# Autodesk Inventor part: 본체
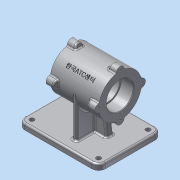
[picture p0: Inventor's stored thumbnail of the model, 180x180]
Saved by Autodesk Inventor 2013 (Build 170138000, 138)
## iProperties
Created: 2015-12
Part Number: 본체
Material: 알루미늄 6061
Document SubType Name: Modeling
Designer: Administrator
Density: 2.71 g/cm^3
Mass: 1142.91 g
Surface Area: 797.148 cm^2
Volume: 421.737 cm^3
Author: Administrator
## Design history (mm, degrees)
sketch "스케치1"
  geometry: L1 (-70, 55)-(70, 55); L2 (70, 55)-(70, -55); L3 (70, -55)-(-70, -55); L4 (-70, -55)-(-70, 55); 3 further points
  constraints: 8 end point, 2 midpoint, 2 parallel, 1 horizontal, 1 horizontal alignment, 1 perpendicular, 1 vertical alignment
  dimensions: "d0" = 140 distance of L1.start L1.end; "d2" = 110 distance of L1.end L2.end
extrude "돌출1" new body sketch "스케치1" distance "d3" = 10; taper "d4" = 0 deg
node "작업 평면1"
sketch "스케치2"
  geometry: L1 (0, 110)-(0, 0) reference; C1 r 37 at (80, 55); 2 further points
  constraints: 1 centre point, 1 horizontal alignment, 1 midpoint
  dimensions: "d6" = 74 diameter of C1; "d111" = 80 distance of point (0, 55) C1.centre
extrude "돌출2" join sketch "스케치2" stored distance "d8" = 85; taper "d9" = 0 deg
sketch "스케치3"
  geometry: L1 (0, 0)-(0, 110) reference; L2 (0, 0)-(10, 0) reference; L3 (10, 110)-(10, 0) reference; L4 (0, 110)-(10, 110) reference; L5 (0, 110)-(10, 110) reference; L6 (10, 110)-(10, 0) reference; L7 (10, 0)-(0, 0) reference; L8 (0, 0)-(0, 110) reference; L9 (10, 18)-(80, 18); L10 (10, 92)-(80, 92); L11 (80, 18)-(80, 92); A1 r 37 centre (80, 55) between (80, 92) and (80, 18) reference; 1 further point
  constraints: 6 end point, 2 perpendicular, 2 point on circle, 2 point on line, 2 tangent, 1 parallel
extrude "돌출3" join sketch "스케치3" stored distance "d10" = 8; taper "d11" = 0 deg
sketch "스케치4"
  geometry: L1 (70, 10)-(70, 0) reference; L2 (70, 0)-(-70, 0) reference; L3 (-70, 0)-(-70, 10) reference; L4 (-70, 10)-(-14, 10) reference; L5 (-14, 10)-(-14, 43) reference; L6 (-14, 43)-(-52.5, 43) reference; L7 (-52.5, 43)-(-52.5, 117) reference; L8 (-52.5, 117)-(32.5, 117) reference; L9 (32.5, 117)-(32.5, 43) reference; L10 (32.5, 43)-(-6, 43) reference; L11 (-6, 43)-(-6, 10) reference; L12 (-6, 10)-(70, 10) reference; L13 (-28.245, 65.019)-(8.245, 65.019); L14 (-28.245, 65.019)-(-35, 10); L15 (8.245, 65.019)-(15, 10); L16 (-35, 10)-(15, 10); 3 further points
  constraints: 8 end point, 2 midpoint, 2 point on line, 1 collinear, 1 parallel, 1 vertical alignment
  dimensions: "d15" = 97 deg angle of L4 L14; "d16" = 97 deg angle of L12 L15; "d17" = 50 distance of L15.end L14.end; "d19" = 55.01908 distance between parallel lines of L12 L13
extrude "돌출4" join sketch "스케치4" stored distance "d20" = 12; taper "d21" = 0 deg
sketch "스케치5"
  geometry: L1 (70, -55)-(70, 55) reference; L2 (70, 55)-(80, 55) reference; L3 (80, 55)-(80, -55) reference; L4 (80, -55)-(70, -55) reference; L5 (-37, -7)-(-36.332, -7); L6 (-37, 7)-(-36.332, 7); A1 r 37 centre (0, 0) between (-37, 0) and (-36.332, -7) reference; A2 r 7 centre (-37, 0) between (-37, 7) and (-37, -7); 1 further point
  constraints: 5 point on circle, 4 end point, 2 parallel, 2 tangent, 1 centre point, 1 horizontal alignment
  dimensions: "d22" = 14 diameter of A2
extrude "돌출5" join sketch "스케치5" distance "d25" = 15; taper "d26" = 0 deg
feature "면 기울기1" dims angle "d27" = 20 deg
hole "구멍1" diameter "d33" = 42; stored, may be unused: countersink angle "d37" = 90 deg, drill point angle "d39" = 0 deg; dims "d31" = 10, "d32" = 10, "d34" = 6, "d35" = 47, "d36" = 22, "d38" = 63
hole "구멍2" diameter "d42" = 47; stored, may be unused: countersink angle "d46" = 90 deg, drill point angle "d48" = 0 deg; dims "d40" = 10, "d41" = 10, "d43" = 6, "d44" = 47, "d45" = 22, "d47" = 22
hole "구멍3" diameter "d51" = 3.242; stored, may be unused: countersink angle "d55" = 90 deg, drill point angle "d57" = 118 deg; dims "d49" = 10, "d50" = 10, "d52" = 9, "d53" = 47, "d54" = 22, "d56" = 11
hole "구멍4" diameter "d63" = 3.242; stored, may be unused: countersink angle "d67" = 90 deg, drill point angle "d69" = 118 deg; dims "d61" = 10, "d62" = 10, "d64" = 9, "d65" = 47, "d66" = 22, "d68" = 11
sketch "스케치6"
  geometry: L1 (6, -6)-(-15, -6) reference; L2 (-15, -6)-(-15, 6) reference; L3 (-15, 6)-(6, 6) reference; L4 (6, 6)-(6, 37) reference; L5 (6, 37)-(14, 37) reference; L6 (14, 37)-(14, 6) reference; L7 (14, 6)-(35, 6) reference; L8 (35, 6)-(35, -6) reference; L9 (35, -6)-(14, -6) reference; L10 (14, -6)-(14, -37) reference; L11 (14, -37)-(6, -37) reference; L12 (6, -37)-(6, -6) reference; L13 (70, 55)-(70, -55) reference; L14 (70, -55)-(-70, -55) reference; L15 (-70, -55)-(-70, 55) reference; L16 (-70, 55)-(70, 55) reference; C1 r 4 at (-58, 43); C2 r 4 at (58, 43); C3 r 4 at (-58, -43); C4 r 4 at (58, -43); 1 further point
  constraints: 4 centre point, 3 equal radius, 2 horizontal alignment, 2 vertical alignment
  dimensions: "d73" = 12 distance from line of C1.centre L15; "d74" = 12 distance from line of L16 C1.centre; "d76" = 116 distance of C2.centre C1.centre; "d77" = 86 distance of C1.centre C3.centre; "d78" = 8 diameter of C1
  node "절단 모서리 투영4"
extrude "돌출6" cut sketch "스케치6" stored distance "d79" = 15; taper "d80" = 0 deg
extrude "돌출7" cut sketch "스케치6" stored distance "d81" = 15; taper "d82" = 0 deg
extrude "돌출8" cut sketch "스케치6" stored distance "d83" = 15; taper "d84" = 0 deg
extrude "돌출9" cut sketch "스케치6" distance "d85" = 15; taper "d86" = 0 deg
fillet "모깎기1" dims "d87" = 12
fillet "모깎기2" dims "d88" = 3
fillet "모깎기3" dims "d89" = 3
fillet "모깎기4" dims "d90" = 3
fillet "모깎기5" dims "d91" = 3
fillet "모깎기6" dims "d92" = 3
fillet "모깎기7" dims "d93" = 3
fillet "모깎기8" dims "d94" = 3
fillet "모깎기9" dims "d95" = 3
fillet "모깎기10" dims "d96" = 0.3
chamfer "모따기1" distance "d97" = 1; stored, may be unused: second distance "d98" = 2, angle "d99" = 45 deg
sketch "스케치10"
  geometry: L1 (13, 92)-(80, 92) reference; L2 (80, 18)-(13, 18) reference; L3 (10, 15)-(10, 3) reference; L4 (7, 0)-(0, 0) reference; L5 (0, 0)-(0, 110) reference; L6 (0, 110)-(7, 110) reference; L7 (10, 107)-(10, 95) reference; C1 r 21 at (80, 55) reference; A1 r 3 centre (13, 95) between (10, 95) and (13, 92) reference; A2 r 37 centre (80, 55) between (80, 18) and (80, 92) reference; A3 r 3 centre (13, 15) between (13, 18) and (10, 15) reference; A4 r 3 centre (7, 3) between (7, 0) and (10, 3) reference; A5 r 3 centre (7, 107) between (10, 107) and (7, 110) reference; 3 further points
  constraints: 1 coincident, 1 point on circle
  dimensions: "d106" = 45 deg dimension on A2.centre point (106.163, 28.837) point (80, 18)
  node "절단 모서리 투영7"
node "작업 평면3"
sketch "스케치11"
  geometry: L1 (-24.887, 3.602)-(24.887, 3.602); L2 (24.887, 3.602)-(24.887, -3.602); L3 (24.887, -3.602)-(-24.887, -3.602); L4 (-24.887, -3.602)-(-24.887, 3.602); 5 further points
  constraints: 2 midpoint, 1 coincident, 1 horizontal alignment, 1 vertical, 1 vertical alignment, 2 other
  dimensions: "d107" = 49.77477 distance from line of L1.end L4; "d108" = 3.60244 distance from line of point (-24.887, 0) L1
feature "엠보싱2" sketch "스케치11" dims "d109" = 0.5, "d110" = 0
node "솔리드1"
pattern_circular "원형 패턴1" dims angle "d29" = 360 deg
mirror "대칭1"
pattern_circular "원형 패턴2" dims angle "d59" = 360 deg
pattern_circular "원형 패턴3" dims angle "d71" = 360 deg
node "투영된 루프1"
node "절단 모서리 투영1"
node "절단 모서리 투영2"
node "절단 모서리 투영3"
